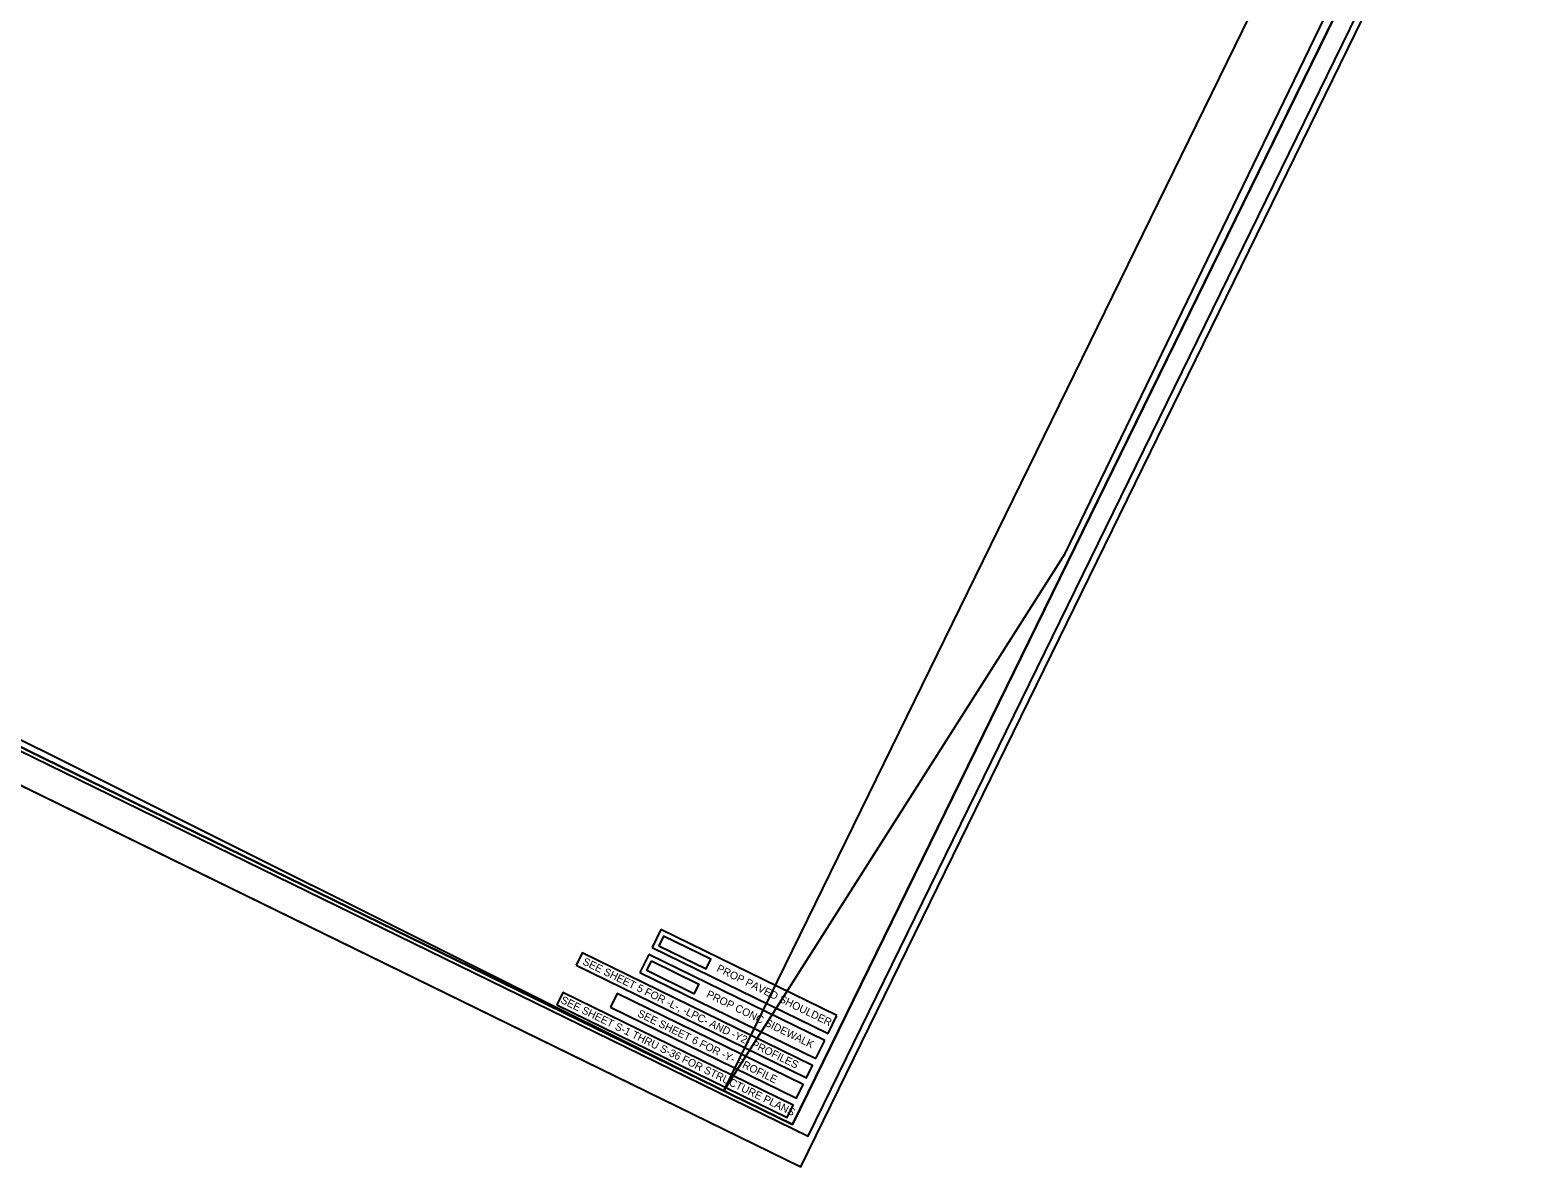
# Model space of a CAD drawing. Extents: x 1519210 to 1521378, y 637447 to 639183.
# Drawn here: x 1520219 to 1521203, y 637460 to 638202 of the extents above; entities that cross this region are included whole.
import ezdxf

# ---------------------------------------------------------------- set-up
doc = ezdxf.new("R2010")
doc.units = 0
for name, color, linetype in [('Prop DSN Text', 7, 'Continuous'), ('Prop Grid Mask', 7, 'Continuous'), ('Prop Shade Light', 7, 'Continuous'), ('Prop Shade Medium', 7, 'Continuous'), ('Sheet Clip Boundary CELL', 7, 'Continuous'), ('Sheet Cutting Line CELL', 7, 'Continuous'), ('Sheet Layout Plan Border', 7, 'Continuous'), ('Sheet Plan CELL', 7, 'Continuous'), ('Sheet Plan Layout CELL', 7, 'Continuous'), ('Sheet Plot Border Inside CELL', 7, 'Continuous'), ('Sheet Plot Border Outside CELL', 7, 'Continuous')]:
    doc.layers.add(name, color=color, linetype=linetype)

msp = doc.modelspace()

# ---------------------------------------------------------------- linework, layer by layer
at = {"layer": 'Prop Grid Mask'}
for p, q in [((1520630.83, 637614.52), (1520625.09, 637602.77)), ((1520745.73, 637558.32), (1520630.83, 637614.52)), ((1520622.89, 637598.28), (1520617.15, 637586.54)), ((1520737.79, 637542.09), (1520622.89, 637598.28)), ((1520625.09, 637602.77), (1520739.98, 637546.58)), ((1520617.15, 637586.54), (1520732.04, 637530.35)), ((1520739.98, 637546.58), (1520745.73, 637558.32)), ((1520732.04, 637530.35), (1520737.79, 637542.09))]:
    msp.add_line(p, q, dxfattribs=at)
for points in [[(1520575.52, 637591.31), (1520725.89, 637517.77), (1520729.85, 637525.86), (1520579.48, 637599.4)], [(1520562.86, 637565.42), (1520713.23, 637491.88), (1520717.18, 637499.96), (1520566.81, 637573.5)], [(1520597.87, 637563.88), (1520719.38, 637504.45), (1520723.7, 637513.28), (1520602.19, 637572.71)]]:
    msp.add_lwpolyline(points, close=True, dxfattribs=at)
at = {"layer": 'Prop Shade Light'}
msp.add_lwpolyline([(1520624.7, 637594.04), (1520655.53, 637578.96), (1520652.44, 637572.64), (1520621.61, 637587.72)], close=True, dxfattribs=at)
at = {"layer": 'Prop Shade Medium'}
msp.add_lwpolyline([(1520629.55, 637603.95), (1520660.38, 637588.87), (1520663.47, 637595.2), (1520632.64, 637610.27)], close=True, dxfattribs=at)
at = {"layer": 'Sheet Clip Boundary CELL'}
msp.add_lwpolyline([(1519956.23, 637866.66), (1520671.92, 637509.27), (1520894.79, 637860.14), (1521077.44, 638237.75), (1521090.11, 638267.88), (1521090.34, 638272.49), (1520913.04, 638361.6), (1520771.34, 638396.31), (1520789.23, 638433.99), (1520863.92, 638574.09), (1520386.4, 638798.91), (1520331.06, 638791.96), (1519849.49, 639022.82)], dxfattribs=at)
at = {"layer": 'Sheet Cutting Line CELL'}
msp.add_line((1519209.9, 638199.25), (1520722.21, 637459.61), dxfattribs=at)
at = {"layer": 'Sheet Layout Plan Border'}
msp.add_lwpolyline([(1519414.26, 638124.36), (1520671.92, 637509.27), (1521040.32, 638262.52), (1520870.3, 638345.67), (1520963.21, 638535.65), (1519875.58, 639067.59)], close=True, dxfattribs=at)
at = {"layer": 'Sheet Plan CELL'}
for points in [[(1521178.17, 638430.52), (1519830.66, 639089.56), (1519369.35, 638146.33), (1520716.83, 637487.3)], [(1519369.35, 638146.33), (1519830.63, 639089.55), (1520998.45, 638518.44), (1520906.34, 638330.09), (1521086.04, 638242.2), (1520716.83, 637487.3)]]:
    msp.add_lwpolyline(points, close=True, dxfattribs=at)
at = {"layer": 'Sheet Plan Layout CELL'}
msp.add_lwpolyline([(1519830.63, 639089.55), (1519369.35, 638146.33), (1520716.82, 637487.31), (1521085.22, 638240.56), (1520870.3, 638345.67), (1520963.21, 638535.65)], close=True, dxfattribs=at)
at = {"layer": 'Sheet Plot Border Inside CELL'}
msp.add_lwpolyline([(1519230.36, 638211.5), (1520726.95, 637479.57), (1521190.47, 638427.28), (1519693.87, 639159.23)], close=True, dxfattribs=at)
at = {"layer": 'Sheet Plot Border Outside CELL'}
msp.add_lwpolyline([(1519209.9, 638199.25), (1520722.21, 637459.61), (1521203.3, 638443.27), (1519690.98, 639182.91)], close=True, dxfattribs=at)

# ---------------------------------------------------------------- texts
at = {"layer": 'Prop DSN Text'}
for s, rotation, p in [('SEE SHEET 5 FOR -L-, -LPC- AND -Y2- PROFILES', 333.93772, (1520579.28, 637591.97)), ('PROP PAVED SHOULDER', 333.93773, (1520666.79, 637587.53)), ('SEE SHEET S-1 THRU S-36 FOR STRUCTURE PLANS', 333.93772, (1520564.95, 637566.89)), ('PROP CONC SIDEWALK', 333.93773, (1520660.08, 637570.69)), ('SEE SHEET 6 FOR -Y- PROFILE', 333.93772, (1520615.15, 637558.06))]:
    msp.add_text(s, height=5, rotation=rotation, dxfattribs=at).set_placement(p)

doc.saveas('drawing.dxf')
